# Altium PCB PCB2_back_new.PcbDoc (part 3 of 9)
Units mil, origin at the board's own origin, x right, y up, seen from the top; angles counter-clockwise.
Board outline 6299 x 3937 mil, 4 copper layers (TopLayer, GROUND, VCC, BottomLayer); 253 components, 421 nets, 2085 pads, 712 vias.
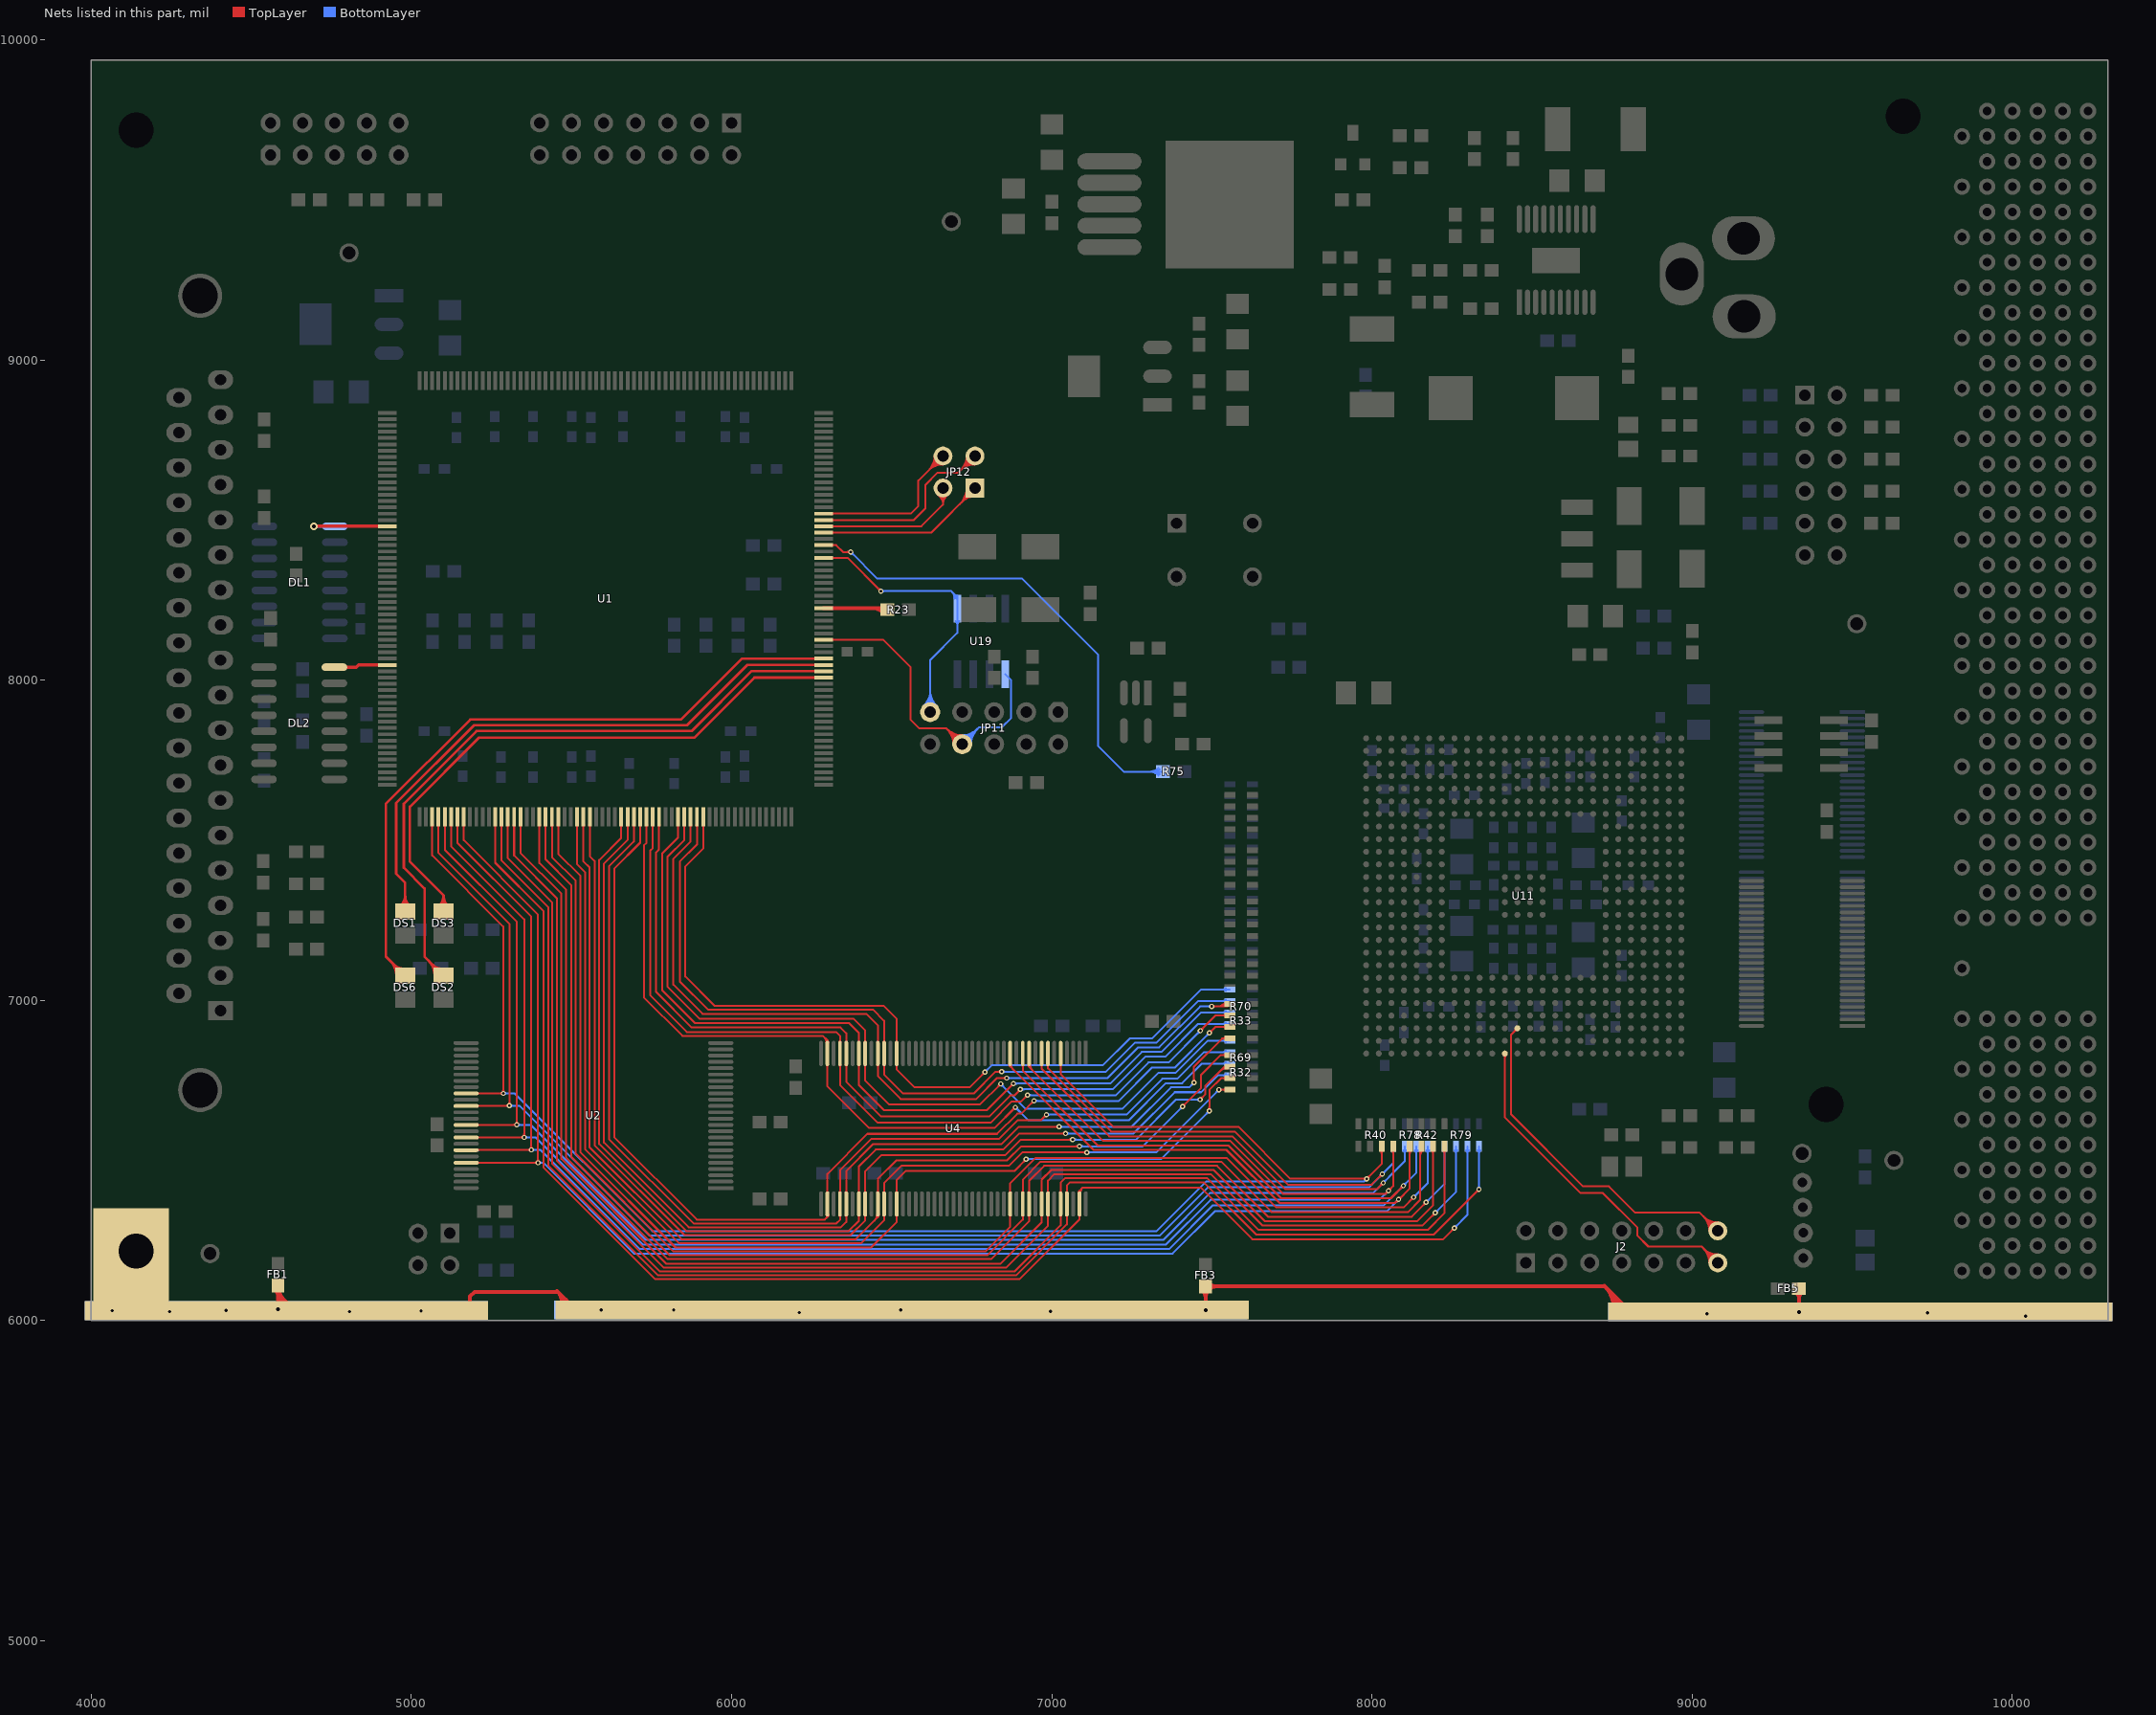
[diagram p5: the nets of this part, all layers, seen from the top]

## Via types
v1: diameter 16, hole 8, TopLayer to BottomLayer, 311 vias
v2: diameter 20, hole 10, TopLayer to BottomLayer, 202 vias
v3: diameter 24, hole 12, TopLayer to BottomLayer, 179 vias
v4: diameter 40, hole 20, TopLayer to BottomLayer, 12 vias
v5: diameter 30, hole 15, TopLayer to BottomLayer, 8 vias

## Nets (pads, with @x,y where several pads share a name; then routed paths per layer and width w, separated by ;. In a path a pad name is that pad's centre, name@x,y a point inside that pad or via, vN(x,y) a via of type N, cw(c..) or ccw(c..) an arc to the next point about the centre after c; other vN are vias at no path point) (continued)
ED02: R40.7 U1.183 U2.33 U4.5 | length 5471.8
  TopLayer w6: U1.183@5062.61,7547.22 cw(c5057.65,7542.26) 5064.66,7542.26 cw(c5071.68,7542.26) U1.183@5066.72,7547.22 ; U1.183@5064.66,7585.69 5064.66,7452.34 5286.73,7230.27 v1(5286.73,6709.27) U2.33@5170.72,6709.27 ; U2.33@5206.24,6707.22 cw(c5211.2,6702.26) 5211.2,6709.28 cw(c5211.2,6716.29) U2.33@5206.24,6711.33 ; v1@5283.19,6705.74 ccw(c5274.65,6697.2) 5274.65,6709.28 ccw(c5274.65,6721.35) 5283.19,6712.81 ccw(c5274.65,6721.35) 5286.73,6721.35 ccw(c5298.8,6721.35) v1@5290.26,6712.81 ; U4.5@7025.21,6798.48 cw(c7020.25,6793.52) 7027.26,6793.52 cw(c7034.27,6793.52) U4.5@7029.31,6798.48 ; U4.5@7027.26,6834 7027.26,6769.74 7193,6604 7584,6604 7745,6443 v1(7984,6443) 8030,6489 R40.7@8030,6543.84 ; v1@7980.46,6439.46 ccw(c7971.93,6430.93) 7971.93,6443 ccw(c7971.93,6455.07) v1@7980.46,6446.54 ; v1@7984,6448 ccw(c7984,6460.07) 7992.54,6451.54 ccw(c8001.07,6443) v1@7989,6443 ; R40.7@8025.76,6531.1 cw(c8015.51,6520.86) 8030,6520.86 cw(c8044.49,6520.86) R40.7@8034.24,6531.1
  BottomLayer w6: v1(5286.73,6709.27) 5321.73,6709.27 5752,6279 7327,6279 7483,6435 7976,6435 ; v1@5290.26,6705.74 cw(c5298.8,6697.2) 5298.8,6709.28 cw(c5298.8,6721.35) v1@5290.26,6712.81 ; v1@7979.01,6442.77 cw(c7968.72,6442.28) 7976,6435 ; v1@7983.77,6438.01 ccw(c7983.28,6427.72) 7976,6435 ; v1(7984,6443) 7976,6435
ED03: R78.8 U1.184 U2.35 U4.7 | length 5638.9
  TopLayer w6: U1.184@5082.29,7547.22 cw(c5077.33,7542.26) 5084.35,7542.26 cw(c5091.36,7542.26) U1.184@5086.4,7547.22 ; U1.184@5084.35,7585.69 5084.35,7460.65 5306,7239 v1(5306,6671) 5171.82,6671 U2.35@5170.72,6669.9 ; U2.35@5206.24,6667.85 cw(c5213.85,6660.25) 5213.85,6671 ; v1@5302.46,6667.46 ccw(c5293.93,6658.93) 5293.93,6671 ccw(c5293.93,6683.07) 5302.46,6674.54 ccw(c5293.93,6683.07) 5306,6683.07 ccw(c5318.07,6683.07) v1@5309.54,6674.54 ; U4.7@6985.84,6798.48 cw(c6980.88,6793.52) 6987.89,6793.52 cw(c6994.9,6793.52) U4.7@6989.94,6798.48 ; U4.7@6987.89,6834 6987.89,6787.11 7185,6590 7571,6590 7737,6424 7999,6424 v1(8032,6457) ; v1@8027,6457 cw(c8014.93,6457) 8023.46,6448.46 cw(c8032,6439.93) v1@8032,6452
  BottomLayer w6: v1(5306,6671) 5337,6671 5743,6265 7336,6265 7487,6416 7991,6416 8066,6491 R78.8@8066,6543.84 ; v1@5309.54,6667.46 cw(c5318.07,6658.93) 5318.07,6671 cw(c5318.07,6683.07) v1@5309.54,6674.54 ; v1@8027,6457 cw(c8014.93,6457) 8023.46,6448.46 cw(c8032,6439.93) v1@8032,6452 ; v1@8032,6462 ccw(c8032,6474.07) 8040.54,6465.54 ccw(c8049.07,6457) v1@8037,6457 ; R78.8@8061.76,6531.1 cw(c8051.51,6520.86) 8066,6520.86 cw(c8080.49,6520.86) R78.8@8070.24,6531.1
ED04: R78.7 U1.185 U2.38 U4.8 | length 5744.6
  TopLayer w6: U1.185@5101.98,7547.22 cw(c5097.02,7542.26) 5104.03,7542.26 cw(c5111.05,7542.26) U1.185@5106.09,7547.22 ; U1.185@5104.03,7585.69 5104.03,7469.97 5329,7245 v1(5329,6611) U2.38@5170.72,6610.85 ; U2.38@5206.25,6608.8 cw(c5211.29,6603.77) 5211.28,6610.89 ; U2.38@5206.24,6612.91 ccw(c5211.12,6617.79) 5211.13,6610.89 ; v1@5325.47,6607.46 ccw(c5316.94,6598.92) 5316.93,6610.99 ccw(c5316.92,6623.06) 5325.46,6614.53 ccw(c5316.93,6623.07) 5329,6623.07 ccw(c5341.07,6623.07) v1@5332.54,6614.54 ; U4.8@6966.15,6798.48 cw(c6961.19,6793.52) 6968.2,6793.52 cw(c6975.22,6793.52) U4.8@6970.26,6798.48 ; U4.8@6968.2,6834 6968.2,6785.8 7179,6575 7564,6575 7729,6410 8015,6410 v1(8035,6430) ; v1@8030,6430 cw(c8017.93,6430) 8026.46,6421.46 cw(c8035,6412.93) v1@8035,6425
  BottomLayer w6: v1(5329,6611) 5372.15,6610.85 5731,6252 7348,6252 7494,6398 8003,6398 8102,6497 R78.7@8102,6543.84 ; v1@5332.52,6607.45 cw(c5341.03,6598.89) 5341.07,6610.96 cw(c5341.11,6623.03) v1@5332.55,6614.52 ; v1@8030,6430 cw(c8017.93,6430) 8026.46,6421.46 cw(c8035,6412.93) v1@8035,6425 ; v1@8035,6435 ccw(c8035,6447.07) 8043.54,6438.54 ccw(c8052.07,6430) v1@8040,6430 ; R78.7@8097.76,6531.1 cw(c8087.51,6520.86) 8102,6520.86 cw(c8116.49,6520.86) R78.7@8106.24,6531.1
ED05: R40.8 U1.186 U2.40 U4.10 | length 5883.2
  TopLayer w6: U1.186@5121.66,7547.22 cw(c5116.7,7542.26) 5123.72,7542.26 cw(c5130.73,7542.26) U1.186@5125.77,7547.22 ; U1.186@5123.72,7585.69 5123.72,7481.28 5352,7253 v1(5352,6572) 5171.24,6572 U2.40@5170.72,6571.48 ; U2.40@5206.24,6569.43 cw(c5212.46,6563.21) 5212.46,6572 ; v1@5348.46,6568.46 ccw(c5339.93,6559.93) 5339.93,6572 ccw(c5339.93,6584.07) 5348.46,6575.54 ccw(c5339.93,6584.07) 5352,6584.07 ccw(c5364.07,6584.07) v1@5355.54,6575.54 ; U4.10@6925.74,6800.54 ccw(c6938.88,6800.54) 6929.59,6791.25 ; U4.10@6928.84,6834 6928.84,6792 7159.84,6561 7557,6561 7722,6396 8042,6396 8066,6420 R40.8@8066,6543.84 ; U4.10@6931.74,6800.54 ccw(c6959.36,6800.54) 6939.83,6781 ; v1@8046.45,6405.45 cw(c8034.38,6405.45) 8042.92,6396.92 cw(c8051.45,6388.38) v1@8051.45,6400.45 ; v1@8051.45,6410.45 ccw(c8051.45,6422.53) 8059.99,6413.99 ccw(c8068.53,6405.45) v1@8056.45,6405.45 ; R40.8@8061.76,6531.1 cw(c8051.51,6520.86) 8066,6520.86 cw(c8080.49,6520.86) R40.8@8070.24,6531.1 ; 6928.84,6793.52 ccw(c6921.82,6793.52) 6926.78,6798.48 cw(c6921.82,6793.52) 6928.84,6793.52 ; 6928.84,6793.52 cw(c6935.85,6793.52) 6930.89,6798.48 ccw(c6935.85,6793.52) 6928.84,6793.52
  BottomLayer w6: v1(5352,6572) 5387,6572 5722,6237 7356,6237 7496,6377 8023,6377 v1(8051.45,6405.45) ; v1@5355.54,6568.46 cw(c5364.07,6559.93) 5364.07,6572 cw(c5364.07,6584.07) v1@5355.54,6575.54 ; v1@8046.45,6405.45 cw(c8034.38,6405.45) 8042.92,6396.92 cw(c8051.45,6388.38) v1@8051.45,6400.45
ED06: R78.6 U1.187 U2.42 U4.11 | length 6015.5
  TopLayer w6: U1.187@5141.35,7547.22 cw(c5136.39,7542.26) 5143.4,7542.26 cw(c5150.42,7542.26) U1.187@5145.46,7547.22 ; U1.187@5143.4,7585.69 5143.4,7491.6 5374,7261 v1(5374,6533) 5171.61,6533 U2.42@5170.72,6532.11 ; U2.42@5206.24,6530.06 cw(c5213.35,6522.95) 5213.35,6533 ; v1@5370.46,6529.46 ccw(c5361.93,6520.93) 5361.93,6533 ccw(c5361.93,6545.07) 5370.46,6536.54 ccw(c5361.93,6545.07) 5374,6545.07 ccw(c5386.07,6545.07) v1@5377.54,6536.54 ; U4.11@6907.1,6798.48 cw(c6902.14,6793.52) 6909.15,6793.52 cw(c6916.16,6793.52) U4.11@6911.2,6798.48 ; U4.11@6909.15,6834 6909.15,6780.85 7143,6547 7551,6547 7716,6382 8059,6382 v1(8098,6421) ; v1@8093,6421 cw(c8080.93,6421) 8089.46,6412.46 cw(c8098,6403.93) v1@8098,6416
  BottomLayer w6: v1(5374,6533) 5403,6533 5713,6223 7366,6223 7503,6360 8037,6360 8138,6461 R78.6@8138,6543.84 ; v1@5377.54,6529.46 cw(c5386.07,6520.93) 5386.07,6533 cw(c5386.07,6545.07) v1@5377.54,6536.54 ; v1@8093,6421 cw(c8080.93,6421) 8089.46,6412.46 cw(c8098,6403.93) v1@8098,6416 ; v1@8098,6426 ccw(c8098,6438.07) 8106.54,6429.54 ccw(c8115.07,6421) v1@8103,6421 ; R78.6@8133.76,6531.1 cw(c8123.51,6520.86) 8138,6520.86 cw(c8152.49,6520.86) R78.6@8142.24,6531.1
ED07: R42.5 U1.188 U2.44 U4.13 | length 6112.5
  TopLayer w6: U1.188@5161.03,7547.22 cw(c5156.07,7542.26) 5163.09,7542.26 cw(c5170.1,7542.26) U1.188@5165.14,7547.22 ; U1.188@5163.09,7585.69 5163.09,7499.91 5395,7268 v1(5395,6492.74) U2.44@5170.72,6492.74 ; U2.44@5206.24,6490.69 cw(c5211.2,6485.73) 5211.2,6492.74 cw(c5211.2,6499.75) U2.44@5206.24,6494.79 ; v1@5391.46,6489.2 ccw(c5382.93,6480.67) 5382.93,6492.74 ccw(c5382.93,6504.81) 5391.46,6496.28 ccw(c5382.93,6504.81) 5395,6504.81 ccw(c5407.07,6504.81) v1@5398.54,6496.28 ; U4.13@6866.69,6800.54 ccw(c6876.88,6800.54) 6869.67,6793.33 ; U4.13@6869.78,6834 6869.78,6793.22 7130,6533 7545,6533 7711,6367 8072,6367 v1(8083,6378) ; U4.13@6872.69,6800.54 ccw(c6897.36,6800.54) 6879.91,6783.09 ; v1@8078,6378 cw(c8065.93,6378) 8074.46,6369.46 cw(c8083,6360.93) v1@8083,6373 ; v1@8083,6383 ccw(c8083,6397.49) 8093.24,6387.24 ; v1@8083.5,6377.5 8118,6412 R42.5@8118,6543.84 ; v1@8088,6378 cw(c8097.66,6378) 8090.83,6384.83 ; R42.5@8113.76,6531.1 cw(c8103.51,6520.86) 8118,6520.86 cw(c8132.49,6520.86) R42.5@8122.24,6531.1 ; 6869.78,6793.52 ccw(c6862.77,6793.52) 6867.73,6798.48 cw(c6862.77,6793.52) 6869.78,6793.52 ; 6869.78,6793.52 cw(c6876.79,6793.52) 6871.83,6798.48 ccw(c6876.79,6793.52) 6869.78,6793.52
  BottomLayer w6: v1(5395,6492.74) 5411.26,6492.74 5695,6209 7377,6209 7509,6341 8046,6341 v1(8083,6378) ; v1@5398.54,6489.2 cw(c5407.07,6480.67) 5407.07,6492.74 cw(c5407.07,6504.81) v1@5398.54,6496.28 ; v1@8078,6378 cw(c8065.93,6378) 8074.46,6369.46 cw(c8083,6360.93) v1@8083,6373
ED08: R78.5 U1.202 U4.74 | length 4387.7
  TopLayer w6: U1.202@5436.62,7547.22 cw(c5431.66,7542.26) 5438.68,7542.26 cw(c5445.69,7542.26) U1.202@5440.73,7547.22 ; U1.202@5438.68,7585.69 5438.68,7447.32 5513,7373 5513,6521 5818,6216 6793,6216 6869.78,6292.78 6869.78,6428.78 6949,6508 7546,6508 7701,6353 8098,6353 v1(8130,6385) ; U4.74@6867.73,6328.48 cw(c6862.77,6323.52) 6869.78,6323.52 cw(c6876.79,6323.52) U4.74@6871.83,6328.48 ; U4.74@6867.73,6399.52 ccw(c6862.77,6404.48) 6869.78,6404.48 ccw(c6876.79,6404.48) U4.74@6871.83,6399.52 ; v1@8125,6385 cw(c8112.93,6385) 8121.46,6376.46 cw(c8130,6367.93) v1@8130,6380
  BottomLayer w6: v1(8130,6385) 8174,6429 R78.5@8174,6543.84 ; v1@8130,6390 ccw(c8130,6402.07) 8138.54,6393.54 ccw(c8147.07,6385) v1@8135,6385 ; R78.5@8169.76,6531.1 cw(c8159.51,6520.86) 8174,6520.86 cw(c8188.49,6520.86) R78.5@8178.24,6531.1
ED09: R42.6 U1.201 U4.76 | length 4395.3
  TopLayer w6: U1.201@5416.94,7547.22 cw(c5411.98,7542.26) 5418.99,7542.26 cw(c5426.01,7542.26) U1.201@5421.05,7547.22 ; U1.201@5418.99,7585.69 5418.99,7440.01 5499,7360 5499,6512 5807,6204 6798,6204 6909.15,6315.15 6909.15,6440.15 6965,6496 7529,6496 7686,6339 8113,6339 8150,6376 8150,6539.84 R42.6@8154,6543.84 ; U4.76@6907.1,6328.48 cw(c6902.14,6323.52) 6909.15,6323.52 cw(c6916.16,6323.52) U4.76@6911.2,6328.48 ; U4.76@6907.1,6399.52 ccw(c6902.14,6404.48) 6909.15,6404.48 ccw(c6916.16,6404.48) U4.76@6911.2,6399.52 ; 8150,6511.2 cw(c8178.14,6511.2) R42.6@8158.24,6531.1 ; 8150,6525.69 cw(c8163.66,6525.69) R42.6@8154,6535.34
ED10: R79.8 U1.200 U4.77 | length 4499.7
  TopLayer w6: U1.200@5397.25,7547.22 cw(c5392.29,7542.26) 5399.31,7542.26 cw(c5406.32,7542.26) U1.200@5401.36,7547.22 ; U1.200@5399.31,7585.69 5399.31,7428.69 5482,7346 5482,6510 5800,6192 6811,6192 6928.84,6309.84 6928.84,6435.84 6976,6483 7516,6483 7675,6324 8124,6324 v1(8169,6369) ; U4.77@6926.78,6328.48 cw(c6921.82,6323.52) 6928.84,6323.52 cw(c6935.85,6323.52) U4.77@6930.89,6328.48 ; U4.77@6926.78,6399.52 ccw(c6921.82,6404.48) 6928.84,6404.48 ccw(c6935.85,6404.48) U4.77@6930.89,6399.52 ; v1@8164,6369 cw(c8151.93,6369) 8160.46,6360.46 cw(c8169,6351.93) v1@8169,6364
  BottomLayer w6: v1(8169,6369) 8226,6426 R79.8@8226,6543.84 ; v1@8169,6374 ccw(c8169,6386.07) 8177.54,6377.54 ccw(c8186.07,6369) v1@8174,6369 ; R79.8@8221.76,6531.1 cw(c8211.51,6520.86) 8226,6520.86 cw(c8240.49,6520.86) R79.8@8230.24,6531.1
ED11: R42.7 U1.197 U4.79 | length 4517.8
  TopLayer w6: U1.197@5338.2,7547.22 cw(c5333.24,7542.26) 5340.25,7542.26 cw(c5347.27,7542.26) U1.197@5342.31,7547.22 ; U1.197@5340.25,7585.69 5340.25,7460.75 5468,7333 5468,6505 5795,6178 6840.2,6178 6968.2,6306 6968.2,6440.2 6998,6470 7506,6470 7666,6310 8141,6310 8190,6359 R42.7@8190,6543.84 ; U4.79@6966.15,6328.48 cw(c6961.19,6323.52) 6968.2,6323.52 cw(c6975.22,6323.52) U4.79@6970.26,6328.48 ; U4.79@6966.15,6399.52 ccw(c6961.19,6404.48) 6968.2,6404.48 ccw(c6975.22,6404.48) U4.79@6970.26,6399.52 ; R42.7@8185.76,6531.1 cw(c8175.51,6520.86) 8190,6520.86 cw(c8204.49,6520.86) R42.7@8194.24,6531.1
ED12: R79.7 U1.196 U4.80 | length 4625
  TopLayer w6: U1.196@5318.51,7547.22 cw(c5313.55,7542.26) 5320.57,7542.26 cw(c5327.58,7542.26) U1.196@5322.62,7547.22 ; U1.196@5320.57,7572.9 5320.57,7452.43 5454,7319 5454,6499 5788,6165 6857,6165 6987.89,6295.89 6987.89,6436.89 7008,6457 7497,6457 7657,6297 8158,6297 v1(8197,6336) ; U4.80@6985.84,6328.48 cw(c6980.88,6323.52) 6987.89,6323.52 cw(c6994.9,6323.52) U4.80@6989.94,6328.48 ; U4.80@6985.84,6399.52 ccw(c6980.88,6404.48) 6987.89,6404.48 ccw(c6994.9,6404.48) U4.80@6989.94,6399.52 ; v1@8192,6336 cw(c8179.93,6336) 8188.46,6327.46 cw(c8197,6318.93) v1@8197,6331
  BottomLayer w6: v1(8197,6336) 8262,6401 R79.7@8262,6543.84 ; v1@8197,6341 ccw(c8197,6353.07) 8205.54,6344.54 ccw(c8214.07,6336) v1@8202,6336 ; R79.7@8257.76,6531.1 cw(c8247.51,6520.86) 8262,6520.86 cw(c8276.49,6520.86) R79.7@8266.24,6531.1
ED13: R42.8 U1.195 U4.82 | length 4631.6
  TopLayer w6: U1.195@5298.83,7547.22 cw(c5293.87,7542.26) 5300.88,7542.26 cw(c5307.9,7542.26) U1.195@5302.94,7547.22 ; U1.195@5300.88,7585.69 5300.88,7444.12 5440,7305 5440,6489 5776,6153 6883,6153 7027.26,6297.26 7027.26,6430.26 7042,6445 7484,6445 7646,6283 8174,6283 8226,6335 R42.8@8226,6543.84 ; U4.82@7025.21,6328.48 cw(c7020.25,6323.52) 7027.26,6323.52 cw(c7034.27,6323.52) U4.82@7029.31,6328.48 ; U4.82@7025.21,6399.52 ccw(c7020.25,6404.48) 7027.26,6404.48 ccw(c7034.27,6404.48) U4.82@7029.31,6399.52 ; R42.8@8221.76,6531.1 cw(c8211.51,6520.86) 8226,6520.86 cw(c8240.49,6520.86) R42.8@8230.24,6531.1
ED14: R79.5 U1.194 U4.83 | length 4756.1
  TopLayer w6: U1.194@5279.14,7547.22 cw(c5274.18,7542.26) 5281.2,7542.26 cw(c5288.21,7542.26) U1.194@5283.25,7547.22 ; U1.194@5281.2,7585.69 5281.2,7436.8 5427,7291 5427,6485 5771,6141 6888,6141 7046.94,6299.94 7046.94,6421.94 7056,6431 7476,6431 7639,6268 8192,6268 v1(8334,6410) ; U4.83@7044.89,6328.48 cw(c7039.93,6323.52) 7046.95,6323.52 cw(c7053.96,6323.52) U4.83@7049,6328.48 ; U4.83@7044.89,6399.52 ccw(c7039.93,6404.48) 7046.95,6404.48 ccw(c7053.96,6404.48) U4.83@7049,6399.52 ; v1@8329,6410 cw(c8316.93,6410) 8325.46,6401.46 cw(c8334,6392.93) v1@8334,6405
  BottomLayer w6: R79.5@8329.76,6531.1 cw(c8319.51,6520.86) 8334,6520.86 cw(c8348.49,6520.86) R79.5@8338.24,6531.1 ; v1@8330.46,6413.54 ccw(c8321.93,6422.07) 8334,6422.07 ccw(c8346.07,6422.07) v1@8337.54,6413.54 ; v1(8334,6410) R79.5@8334,6543.84
ED15: R79.6 U1.193 U4.85 | length 4805
  TopLayer w6: U1.193@5259.46,7547.22 cw(c5254.5,7542.26) 5261.51,7542.26 cw(c5268.53,7542.26) U1.193@5263.57,7547.22 ; U1.193@5261.51,7585.69 5261.51,7429.49 5413,7278 5413,6477 5761,6129 6899,6129 7086.31,6316.31 7086.31,6405.31 7096,6415 ; U4.85@7083.22,6397.33 cw(c7093.9,6397.79) 7086.34,6405.34 ; U4.85@7084.26,6328.48 cw(c7079.3,6323.52) 7086.32,6323.52 cw(c7093.33,6323.52) U4.85@7088.37,6328.48 ; U4.85@7084.26,6399.52 ccw(c7079.3,6404.48) 7086.32,6404.48 ccw(c7093.33,6404.48) U4.85@7088.37,6399.52 ; U4.85@7089.22,6397.59 cw(c7112.42,6398.58) 7096,6415 ; v1@8252,6289 cw(c8239.93,6289) 8248.46,6280.46 cw(c8257,6271.93) v1@8257,6284 ; v1(8257,6289) 8222,6254 7626,6254 7465,6415 7096,6415
  BottomLayer w6: v1(8257,6289) 8298,6330 R79.6@8298,6543.84 ; v1@8257,6294 ccw(c8257,6306.07) 8265.54,6297.54 ccw(c8274.07,6289) v1@8262,6289 ; R79.6@8293.76,6531.1 cw(c8283.51,6520.86) 8298,6520.86 cw(c8312.49,6520.86) R79.6@8302.24,6531.1
ED16: R70.8 U1.226 U4.31 | length 2692.1
  TopLayer w6: U1.226@5909.06,7547.22 cw(c5904.1,7542.26) 5911.12,7542.26 cw(c5918.13,7542.26) U1.226@5913.17,7547.22 ; U1.226@5911.12,7585.69 5911.12,7474.12 5855,7418 5855,7074 5946,6983 6474,6983 6515.45,6941.55 6515.45,6783.55 6571,6728 6743,6728 v1(6791,6776) ; U4.31@6513.4,6798.48 cw(c6508.44,6793.52) 6515.45,6793.52 cw(c6522.46,6793.52) U4.31@6517.5,6798.48 ; U4.31@6513.4,6869.52 ccw(c6508.44,6874.48) 6515.45,6874.48 ccw(c6522.46,6874.48) U4.31@6517.5,6869.52 ; v1@6786,6776 cw(c6773.93,6776) 6782.46,6767.46 cw(c6791,6758.93) v1@6791,6771
  BottomLayer w6: v1(6791,6776) 6812,6797 7159,6797 7243,6881 7313,6881 7466,7034 R70.8@7555.84,7034 ; v1@6791,6781 ccw(c6791,6793.07) 6799.54,6784.54 ccw(c6808.07,6776) v1@6796,6776 ; R70.8@7543.1,7029.76 ccw(c7532.86,7019.51) 7532.86,7034 ccw(c7532.86,7048.49) R70.8@7543.1,7038.24
ED17: R70.7 U1.225 U4.33 | length 2723.5
  TopLayer w6: U1.225@5889.38,7547.22 cw(c5884.42,7542.26) 5891.43,7542.26 cw(c5898.45,7542.26) U1.225@5893.49,7547.22 ; U1.225@5891.43,7585.69 5891.43,7486.43 5838,7433 5838,7059 5926,6971 6441,6971 6476.08,6935.92 6476.08,6767.92 6535,6709 6756,6709 6824,6777 v1(6843,6777) ; U4.33@6474.03,6798.48 cw(c6469.07,6793.52) 6476.08,6793.52 cw(c6483.09,6793.52) U4.33@6478.13,6798.48 ; U4.33@6474.03,6869.52 ccw(c6469.07,6874.48) 6476.08,6874.48 ccw(c6483.09,6874.48) U4.33@6478.13,6869.52 ; v1@6839.46,6773.46 ccw(c6830.93,6764.93) 6830.93,6777 ccw(c6830.93,6789.07) v1@6839.46,6780.54
  BottomLayer w6: v1(6843,6777) 7169,6777 7259,6867 7326,6867 7457,6998 R70.7@7555.84,6998 ; v1@6846.54,6773.46 cw(c6855.07,6764.93) 6855.07,6777 cw(c6855.07,6789.07) v1@6846.54,6780.54 ; R70.7@7543.1,6993.76 ccw(c7532.86,6983.51) 7532.86,6998 ccw(c7532.86,7012.49) R70.7@7543.1,7002.24
ED18: R33.5 U1.224 U4.34 | length 2833.5
  TopLayer w6: U1.224@5869.69,7547.22 cw(c5864.73,7542.26) 5871.75,7542.26 cw(c5878.76,7542.26) U1.224@5873.8,7547.22 ; U1.224@5871.75,7585.69 5871.75,7495.75 5818,7442 5818,7049 5909,6958 6420,6958 6456.4,6921.6 6456.4,6763.6 6528,6692 6764,6692 6829,6757 v1(6859,6757) ; U4.34@6454.34,6798.48 cw(c6449.38,6793.52) 6456.4,6793.52 cw(c6463.41,6793.52) U4.34@6458.45,6798.48 ; U4.34@6454.34,6869.52 ccw(c6449.38,6874.48) 6456.4,6874.48 ccw(c6463.41,6874.48) U4.34@6458.45,6869.52 ; v1@6855.46,6753.46 ccw(c6846.93,6744.93) 6846.93,6757 ccw(c6846.93,6769.07) v1@6855.46,6760.54 ; v1(7499,6981) 7547.84,6981 R33.5@7555.84,6989 ; v1@7502.54,6977.46 cw(c7511.07,6968.93) 7511.07,6981 cw(c7511.07,6993.07) v1@7502.54,6984.54 ; 7513.54,6981 ccw(c7513.54,7022.8) R33.5@7543.1,6993.24 ; 7528.03,6981 ccw(c7528.03,7008.31) R33.5@7547.34,6989 ; R33.5@7542.51,6981 ccw(c7542.51,6993.83) R33.5@7551.59,6984.76
  BottomLayer w6: v1(6859,6757) 7174,6757 7270,6853 7335,6853 7463,6981 v1(7499,6981) ; v1@6862.54,6753.46 cw(c6871.07,6744.93) 6871.07,6757 cw(c6871.07,6769.07) v1@6862.54,6760.54 ; v1@7495.46,6977.46 ccw(c7486.93,6968.93) 7486.93,6981 ccw(c7486.93,6993.07) v1@7495.46,6984.54
ED19: R69.8 U1.223 U4.36 | length 2805
  TopLayer w6: U1.223@5850.01,7547.22 cw(c5845.05,7542.26) 5852.06,7542.26 cw(c5859.08,7542.26) U1.223@5854.12,7547.22 ; U1.223@5852.06,7585.69 5852.06,7501.06 5800,7449 5800,7042 5899,6943 6380,6943 6417.02,6905.98 6417.02,6748.98 6491,6675 6776,6675 v1(6840,6739) ; U4.36@6414.97,6798.48 cw(c6410.01,6793.52) 6417.03,6793.52 ; U4.36@6414.97,6869.52 ccw(c6410.01,6874.48) 6417.03,6874.48 ; 6417.02,6793.52 cw(c6424.04,6793.52) U4.36@6419.08,6798.48 ; 6417.02,6874.48 ccw(c6424.04,6874.48) U4.36@6419.08,6869.52 ; v1@6835,6739 cw(c6822.93,6739) 6831.46,6730.46 cw(c6840,6721.93) v1@6840,6734
  BottomLayer w6: v1@6840,6734 cw(c6840,6721.93) 6848.54,6730.46 cw(c6857.07,6739) v1@6845,6739 ; v1(6840,6739) 6917,6662 7221,6662 7333,6774 7387,6774 7487,6874 R69.8@7555.84,6874 ; R69.8@7543.1,6869.76 ccw(c7532.86,6859.51) 7532.86,6874 ccw(c7532.86,6888.49) R69.8@7543.1,6878.24
ED20: R70.6 U1.222 U4.37 | length 2817.9
  TopLayer w6: U1.222@5830.32,7547.22 cw(c5825.36,7542.26) 5832.38,7542.26 cw(c5839.39,7542.26) U1.222@5834.43,7547.22 ; U1.222@5832.38,7585.69 5832.38,7508.38 5783,7459 5783,7031 5885,6929 6366,6929 6397.34,6897.66 6397.34,6735.66 6476,6657 6797,6657 v1(6880,6740) ; U4.37@6395.29,6798.48 cw(c6390.33,6793.52) 6397.34,6793.52 cw(c6404.35,6793.52) U4.37@6399.39,6798.48 ; U4.37@6395.29,6869.52 ccw(c6390.33,6874.48) 6397.34,6874.48 ccw(c6404.35,6874.48) U4.37@6399.39,6869.52 ; v1@6875,6740 cw(c6862.93,6740) 6871.46,6731.46 cw(c6880,6722.93) v1@6880,6735
  BottomLayer w6: v1(6880,6740) 7182,6740 7281,6839 7343,6839 7466,6962 R70.6@7555.84,6962 ; v1@6883.54,6736.46 cw(c6892.07,6727.93) 6892.07,6740 cw(c6892.07,6752.07) v1@6883.54,6743.54 ; R70.6@7543.1,6957.76 ccw(c7532.86,6947.51) 7532.86,6962 ccw(c7532.86,6976.49) R70.6@7543.1,6966.24
ED21: R70.5 U1.219 U4.39 | length 2818.4
  TopLayer w6: U1.219@5771.27,7547.22 cw(c5766.31,7542.26) 5773.32,7542.26 cw(c5780.34,7542.26) U1.219@5775.38,7547.22 ; U1.219@5773.32,7585.69 5773.32,7471.32 5764,7462 5764,7026 5875,6915 6340,6915 6357.97,6897.03 6357.97,6746.03 6467,6637 6804,6637 6870,6703 6883,6703 v1(6902,6722) ; U4.39@6355.92,6798.48 cw(c6350.96,6793.52) 6357.97,6793.52 cw(c6364.98,6793.52) U4.39@6360.02,6798.48 ; U4.39@6355.92,6869.52 ccw(c6350.96,6874.48) 6357.97,6874.48 ccw(c6364.98,6874.48) U4.39@6360.02,6869.52 ; v1@6897,6722 cw(c6884.93,6722) 6893.46,6713.46 cw(c6902,6704.93) v1@6902,6717
  BottomLayer w6: v1(6902,6722) 7190,6722 7292,6824 7354,6824 7456,6926 R70.5@7555.84,6926 ; v1@6905.54,6718.46 cw(c6914.07,6709.93) 6914.07,6722 cw(c6914.07,6734.07) v1@6905.54,6725.54 ; R70.5@7543.1,6921.76 ccw(c7532.86,6911.51) 7532.86,6926 ccw(c7532.86,6940.49) R70.5@7543.1,6930.24
ED22: R33.6 U1.218 U4.40 | length 2909
  TopLayer w6: U1.218@5751.58,7547.22 cw(c5746.62,7542.26) 5753.64,7542.26 cw(c5760.65,7542.26) U1.218@5755.69,7547.22 ; U1.218@5753.64,7585.69 5753.64,7475.64 5745,7467 5745,7016 5860,6901 6326,6901 6338.28,6888.72 6338.28,6735.72 6456,6618 6809,6618 6875,6684 6904,6684 v1(6924,6704) ; U4.40@6336.23,6798.48 cw(c6331.27,6793.52) 6338.28,6793.52 cw(c6345.3,6793.52) U4.40@6340.34,6798.48 ; U4.40@6336.23,6869.52 ccw(c6331.27,6874.48) 6338.28,6874.48 ccw(c6345.3,6874.48) U4.40@6340.34,6869.52 ; v1@6919,6704 cw(c6906.93,6704) 6915.46,6695.46 cw(c6924,6686.93) v1@6924,6699 ; v1(7464,6905) 7512,6953 R33.6@7555.84,6953 ; v1@7464,6910 ccw(c7464,6922.07) 7472.54,6913.54 ccw(c7481.07,6905) v1@7469,6905 ; R33.6@7543.1,6948.76 ccw(c7532.86,6938.51) 7532.86,6953 ccw(c7532.86,6967.49) R33.6@7543.1,6957.24
  BottomLayer w6: v1(6924,6704) 7200,6704 7302,6806 7365,6806 v1(7464,6905) ; v1@6927.54,6700.46 cw(c6936.07,6691.93) 6936.07,6704 cw(c6936.07,6716.07) v1@6927.54,6707.54 ; v1@7459,6905 cw(c7446.93,6905) 7455.46,6896.46 cw(c7464,6887.93) v1@7464,6900
ED23: R69.6 U1.217 U4.42 | length 2902.7
  TopLayer w6: U1.217@5731.9,7547.22 cw(c5726.94,7542.26) 5733.95,7542.26 cw(c5740.97,7542.26) U1.217@5736.01,7547.22 ; U1.217@5733.95,7585.69 5733.95,7491.95 5726,7484 5726,7009 5846,6889 6285,6889 6298.91,6875.09 6298.91,6731.09 6429,6601 6821,6601 v1(6886,6666) ; 6288.57,6885.43 cw(c6270.6,6867.46) U4.42@6296.01,6867.46 ; U4.42@6296.86,6798.48 cw(c6291.9,6793.52) 6298.91,6793.52 cw(c6305.93,6793.52) U4.42@6300.97,6798.48 ; U4.42@6296.86,6869.52 ccw(c6291.9,6874.48) 6298.91,6874.48 ccw(c6305.93,6874.48) U4.42@6300.97,6869.52 ; 6298.81,6875.19 cw(c6291.08,6867.46) U4.42@6302.01,6867.46 ; v1@6881,6666 cw(c6868.93,6666) 6877.46,6657.46 cw(c6886,6648.93) v1@6886,6661
  BottomLayer w6: v1@6886,6661 cw(c6886,6648.93) 6894.54,6657.46 cw(c6903.07,6666) v1@6891,6666 ; v1(6886,6666) 6927,6625 7240,6625 7356,6741 7407,6741 7468,6802 R69.6@7555.84,6802 ; R69.6@7543.1,6797.76 ccw(c7532.86,6787.51) 7532.86,6802 ccw(c7532.86,6816.49) R69.6@7543.1,6806.24
ED24: R33.7 U1.216 U4.45 | length 3503.3
  TopLayer w6: U1.216@5712.21,7547.22 cw(c5707.25,7542.26) 5714.27,7542.26 cw(c5721.28,7542.26) U1.216@5716.32,7547.22 ; U1.216@5714.27,7585.69 5714.27,7492.27 5633,7411 5633,6573 5891,6315 6291,6315 6298.91,6322.91 ; 6294.81,6318.81 ccw(c6288.59,6325.03) U4.45@6296.35,6329.17 ; U4.45@6296.86,6399.52 ccw(c6291.9,6404.48) 6298.91,6404.48 ccw(c6305.93,6404.48) U4.45@6300.97,6399.52 ; U4.45@6298.91,6364 6298.91,6457.91 6424,6583 6829,6583 6892,6646 6904,6646 v1(6944,6686) ; 6300.54,6324.54 ccw(c6296.06,6329.01) U4.45@6301.65,6331.99 ; v1@6939,6686 cw(c6926.93,6686) 6935.46,6677.46 cw(c6944,6668.93) v1@6944,6681 ; v1(7492,6898) 7511,6917 R33.7@7555.84,6917 ; v1@7492,6903 ccw(c7492,6915.07) 7500.54,6906.54 ccw(c7509.07,6898) v1@7497,6898 ; R33.7@7543.1,6912.76 ccw(c7532.86,6902.51) 7532.86,6917 ccw(c7532.86,6931.49) R33.7@7543.1,6921.24
  BottomLayer w6: v1(6944,6686) 7209,6686 7313,6790 7384,6790 v1(7492,6898) ; v1@6947.54,6682.46 cw(c6956.07,6673.93) 6956.07,6686 cw(c6956.07,6698.07) v1@6947.54,6689.54 ; v1@7487,6898 cw(c7474.93,6898) 7483.46,6889.46 cw(c7492,6880.93) v1@7492,6893
ED25: R69.7 U1.215 U4.47 | length 3505.2
  TopLayer w6: U1.215@5692.53,7547.22 cw(c5687.57,7542.26) 5694.58,7542.26 cw(c5701.6,7542.26) U1.215@5696.64,7547.22 ; U1.215@5694.58,7585.69 5694.58,7495.58 5617,7418 5617,6567 5881,6303 6327,6303 6338.28,6314.28 6338.28,6469.28 6435.88,6566.88 6834.88,6566.88 6893,6625 6965.12,6625 v1(6983.12,6643) ; U4.47@6336.23,6328.48 cw(c6331.27,6323.52) 6338.28,6323.52 cw(c6345.3,6323.52) U4.47@6340.34,6328.48 ; U4.47@6336.23,6399.52 ccw(c6331.27,6404.48) 6338.28,6404.48 ccw(c6345.3,6404.48) U4.47@6340.34,6399.52 ; v1@6978.12,6643 cw(c6966.05,6643) 6974.59,6634.46 cw(c6983.12,6625.93) v1@6983.12,6638
  BottomLayer w6: v1(6983.12,6643) 7233,6643 7345,6755 7392,6755 7475,6838 R69.7@7555.84,6838 ; v1@6986.66,6639.46 cw(c6995.19,6630.93) 6995.19,6643 cw(c6995.19,6655.07) v1@6986.66,6646.54 ; R69.7@7543.1,6833.76 ccw(c7532.86,6823.51) 7532.86,6838 ccw(c7532.86,6852.49) R69.7@7543.1,6842.24
ED26: R33.8 U1.214 U4.48 | length 3623.4
  TopLayer w6: U1.214@5672.84,7547.22 cw(c5667.88,7542.26) 5674.9,7542.26 cw(c5681.91,7542.26) U1.214@5676.95,7547.22 ; U1.214@5674.9,7585.69 5674.9,7500.9 5601,7427 5601,6556 5866,6291 6341,6291 6357.97,6307.97 6357.97,6466.97 6442,6551 6843,6551 6897,6605 v1(7023,6605) ; U4.48@6355.92,6328.48 cw(c6350.96,6323.52) 6357.97,6323.52 cw(c6364.98,6323.52) U4.48@6360.02,6328.48 ; U4.48@6355.92,6399.52 ccw(c6350.96,6404.48) 6357.97,6404.48 ccw(c6364.98,6404.48) U4.48@6360.02,6399.52 ; v1@7019.46,6601.46 ccw(c7010.93,6592.93) 7010.93,6605 ccw(c7010.93,6617.07) v1@7019.46,6608.54 ; v1@7440.46,6746.54 ccw(c7431.93,6755.07) 7444,6755.07 ccw(c7456.07,6755.07) v1@7447.54,6746.54 ; v1(7444,6743) 7444,6793 7532,6881 R33.8@7555.84,6881 ; R33.8@7543.1,6876.76 ccw(c7532.86,6866.51) 7532.86,6881 ccw(c7532.86,6895.49) R33.8@7543.1,6885.24
  BottomLayer w6: v1(7023,6605) 7249,6605 7372,6728 7429,6728 v1(7444,6743) ; v1@7026.54,6601.46 cw(c7035.07,6592.93) 7035.07,6605 cw(c7035.07,6617.07) v1@7026.54,6608.54 ; v1@7439,6743 cw(c7426.93,6743) 7435.46,6734.46 cw(c7444,6725.93) v1@7444,6738
ED27: R69.5 U1.213 U4.50 | length 3541.1
  TopLayer w6: U1.213@5653.16,7547.22 cw(c5648.2,7542.26) 5655.21,7542.26 cw(c5662.23,7542.26) U1.213@5657.27,7547.22 ; U1.213@5655.21,7585.69 5655.21,7507.21 5586,7438 5586,6551 5858,6279 6365.34,6279 6397.34,6311 6397.34,6481.34 6450,6534 6848,6534 6898,6584 v1(7043,6584) ; U4.50@6395.29,6328.48 cw(c6390.33,6323.52) 6397.34,6323.52 cw(c6404.35,6323.52) U4.50@6399.39,6328.48 ; U4.50@6395.29,6399.52 ccw(c6390.33,6404.48) 6397.34,6404.48 ccw(c6404.35,6404.48) U4.50@6399.39,6399.52 ; v1@7039.46,6580.46 ccw(c7030.93,6571.93) 7030.93,6584 ccw(c7030.93,6596.07) v1@7039.46,6587.54
  BottomLayer w6: v1(7043,6584) 7255,6584 7384,6713 7466,6713 7519,6766 R69.5@7555.84,6766 ; v1@7046.54,6580.46 cw(c7055.07,6571.93) 7055.07,6584 cw(c7055.07,6596.07) v1@7046.54,6587.54 ; R69.5@7543.1,6761.76 ccw(c7532.86,6751.51) 7532.86,6766 ccw(c7532.86,6780.49) R69.5@7543.1,6770.24
ED28: R32.6 U1.208 U4.51 | length 3615.7
  TopLayer w6: U1.208@5554.73,7547.22 cw(c5549.77,7542.26) 5556.79,7542.26 cw(c5563.8,7542.26) U1.208@5558.84,7547.22 ; U1.208@5556.79,7585.69 5556.79,7450.21 5572,7435 5572,6547 5852,6267 6371,6267 6417.02,6313.02 6417.02,6466.02 6467,6516 6854,6516 6903,6565 v1(7065,6565) ; U4.51@6414.97,6328.48 cw(c6410.01,6323.52) 6417.03,6323.52 ; U4.51@6414.97,6399.52 ccw(c6410.01,6404.48) 6417.03,6404.48 ; 6417.02,6323.52 cw(c6424.04,6323.52) U4.51@6419.08,6328.48 ; 6417.02,6404.48 ccw(c6424.04,6404.48) U4.51@6419.08,6399.52 ; v1@7061.46,6561.46 ccw(c7052.93,6552.93) 7052.93,6565 ccw(c7052.93,6577.07) v1@7061.46,6568.54 ; v1(7463,6690) 7479,6706 7479,6732 7540,6793 R32.6@7555.84,6793 ; v1@7463,6695 ccw(c7463,6707.07) 7471.54,6698.54 ccw(c7480.07,6690) v1@7468,6690 ; 7524.57,6777.57 cw(c7547.34,6754.79) R32.6@7547.34,6787 ; 7534.81,6787.81 cw(c7547.34,6775.27) R32.6@7547.34,6793
  BottomLayer w6: v1(7065,6565) 7263,6565 7388,6690 v1(7463,6690) ; v1@7068.54,6561.46 cw(c7077.07,6552.93) 7077.07,6565 cw(c7077.07,6577.07) v1@7068.54,6568.54 ; v1@7459.46,6686.46 ccw(c7450.93,6677.93) 7450.93,6690 ccw(c7450.93,6702.07) v1@7459.46,6693.54
ED29: R32.5 U1.207 U4.53 | length 3665.9
  TopLayer w6: U1.207@5535.05,7547.22 cw(c5530.09,7542.26) 5537.1,7542.26 cw(c5544.12,7542.26) U1.207@5539.16,7547.22 ; U1.207@5537.1,7585.69 5537.1,7433.9 5556,7415 5556,6541 5843,6254 6388,6254 6456.4,6322.4 6456.4,6442.4 6514,6500 6860,6500 6904,6544 v1(7086,6544) ; 6445.68,6311.68 ccw(c6426.82,6330.54) U4.53@6453.49,6330.54 ; U4.53@6454.34,6328.48 cw(c6449.38,6323.52) 6456.4,6323.52 cw(c6463.41,6323.52) U4.53@6458.45,6328.48 ; U4.53@6454.34,6399.52 ccw(c6449.38,6404.48) 6456.4,6404.48 ccw(c6463.41,6404.48) U4.53@6458.45,6399.52 ; 6455.92,6321.92 ccw(c6447.31,6330.54) U4.53@6459.49,6330.54 ; v1@7082.46,6540.46 ccw(c7073.93,6531.93) 7073.93,6544 ccw(c7073.93,6556.07) v1@7082.46,6547.54 ; v1(7408.12,6668.12) 7465,6725 7465,6766 7528,6829 R32.5@7555.84,6829 ; v1@7408.12,6673.12 ccw(c7408.12,6685.19) 7416.65,6676.65 ccw(c7425.19,6668.12) v1@7413.12,6668.12 ; R32.5@7543.1,6824.76 ccw(c7532.86,6814.51) 7532.86,6829 ccw(c7532.86,6843.49) R32.5@7543.1,6833.24
  BottomLayer w6: v1(7086,6544) 7284,6544 v1(7408.12,6668.12) ; v1@7089.54,6540.46 cw(c7098.07,6531.93) 7098.07,6544 cw(c7098.07,6556.07) v1@7089.54,6547.54 ; v1@7403.12,6668.12 cw(c7391.05,6668.12) 7399.58,6659.58 cw(c7408.12,6651.05) v1@7408.12,6663.12
ED30: R32.8 U1.206 U4.54 | length 3594.9
  TopLayer w6: U1.206@5515.36,7547.22 cw(c5510.4,7542.26) 5517.42,7542.26 cw(c5524.43,7542.26) U1.206@5519.47,7547.22 ; U1.206@5517.42,7585.69 5517.42,7424.58 5542,7400 5542,6535 5836,6241 6404,6241 6476.08,6313.08 6476.08,6429 6530.08,6483 6866,6483 6908,6525 v1(7109,6525) ; U4.54@6474.03,6328.48 cw(c6469.07,6323.52) 6476.08,6323.52 cw(c6483.09,6323.52) U4.54@6478.13,6328.48 ; U4.54@6474.03,6399.52 ccw(c6469.07,6404.48) 6476.08,6404.48 ccw(c6483.09,6404.48) U4.54@6478.13,6399.52 ; v1@7105.46,6521.46 ccw(c7096.93,6512.93) 7096.93,6525 ccw(c7096.93,6537.07) v1@7105.46,6528.54 ; v1(7522,6721) R32.8@7555.84,6721 ; v1@7525.54,6717.46 cw(c7534.07,6708.93) 7534.07,6721 cw(c7534.07,6733.07) v1@7525.54,6724.54 ; R32.8@7543.1,6716.76 ccw(c7532.86,6706.51) 7532.86,6721 ccw(c7532.86,6735.49) R32.8@7543.1,6725.24
  BottomLayer w6: v1(7109,6525) 7326,6525 v1(7522,6721) ; v1@7112.54,6521.46 cw(c7121.07,6512.93) 7121.07,6525 cw(c7121.07,6537.07) v1@7112.54,6528.54 ; v1@7517,6721 cw(c7504.93,6721) 7513.46,6712.46 cw(c7522,6703.93) v1@7522,6716
ED31: R32.7 U1.203 U4.56 | length 3706.6
  TopLayer w6: U1.203@5456.31,7547.22 cw(c5451.35,7542.26) 5458.36,7542.26 cw(c5465.38,7542.26) U1.203@5460.42,7547.22 ; U1.203@5458.36,7585.69 5458.36,7457.64 5528,7388 5528,6525 5825,6228 6436,6228 6515.45,6307.45 6515.45,6439.45 6543,6467 6883,6467 v1(6920,6504) ; U4.56@6513.4,6328.48 cw(c6508.44,6323.52) 6515.45,6323.52 cw(c6522.46,6323.52) U4.56@6517.5,6328.48 ; U4.56@6513.4,6399.52 ccw(c6508.44,6404.48) 6515.45,6404.48 ccw(c6522.46,6404.48) U4.56@6517.5,6399.52 ; v1@6915,6504 cw(c6902.93,6504) 6911.46,6495.46 cw(c6920,6486.93) v1@6920,6499 ; v1@7488.46,6658.54 ccw(c7479.93,6667.07) 7492,6667.07 ccw(c7504.07,6667.07) v1@7495.54,6658.54 ; v1(7492,6655) 7492,6720 7529,6757 R32.7@7555.84,6757 ; R32.7@7543.1,6752.76 ccw(c7532.86,6742.51) 7532.86,6757 ccw(c7532.86,6771.49) R32.7@7543.1,6761.24
  BottomLayer w6: v1(6920,6504) 7341,6504 v1(7492,6655) ; v1@6923.54,6500.46 cw(c6932.07,6491.93) 6932.07,6504 cw(c6932.07,6516.07) v1@6923.54,6507.54 ; v1@7487,6655 cw(c7474.93,6655) 7483.46,6646.46 cw(c7492,6637.93) v1@7492,6650
EMU0: J2.13 U11.A15 | length 1325
  TopLayer w6: U11.A15@8410.4,6829.58 cw(c8399.73,6818.91) 8414.82,6818.91 cw(c8429.91,6818.91) U11.A15@8419.24,6829.58 ; U11.A15@8414.82,6834 8414.82,6634.18 8651,6398 8721,6398 8828,6291 8828,6266 8863,6231 9029,6231 J2.13@9080,6180 ; J2.13@9053.47,6180 ccw(c8989.43,6180) 9034.71,6225.29 ccw(c9080,6270.57) J2.13@9080,6206.53 ; J2.13@9059.47,6180 ccw(c9009.91,6180) 9044.96,6215.04 ccw(c9080,6250.09) J2.13@9080,6200.53 ; J2.13@9065.47,6180 ccw(c9030.4,6180) 9055.2,6204.8 ccw(c9080,6229.6) J2.13@9080,6194.53
EMU1: J2.14 U11.C14 | length 1331.1
  TopLayer w6: U11.C14@8447.94,6912.74 cw(c8432.84,6912.74) 8443.52,6902.07 cw(c8454.19,6891.39) U11.C14@8454.19,6906.49 ; U11.C14@8454.19,6912.74 8434,6892.55 8434,6644 8659,6419 8740,6419 8822,6337 9023,6337 J2.14@9080,6280 ; J2.14@9053.47,6280 ccw(c8989.43,6280) 9034.71,6325.29 ccw(c9080,6370.57) J2.14@9080,6306.53 ; J2.14@9059.47,6280 ccw(c9009.91,6280) 9044.96,6315.04 ccw(c9080,6350.09) J2.14@9080,6300.53 ; J2.14@9065.47,6280 ccw(c9030.4,6280) 9055.2,6304.8 ccw(c9080,6329.6) J2.14@9080,6294.53
EN1: DL1.1 U1.139 | length 295.5
  TopLayer w10: v3@4695,8480 v3(4695.38,8480.38) U1.139@4924.9,8480.38
  BottomLayer w10: v3(4695.38,8480.38) 4760.42,8480.38 DL1.1@4760.7,8480.1
EN2: DL2.16 U1.161 | length 168.6
  TopLayer w10: DL2.16@4759.3,8040.1 4827.1,8040.1 4834.31,8047.31 U1.161@4924.9,8047.31
FPGA_ASDO: JP11.9 U1.37 U19.5 | length 1257
  TopLayer w6: U1.37@6274.31,8381.95 6362.05,8381.95 v1(6466,8278) ; U1.37@6312.78,8379.9 cw(c6317.74,8374.94) 6317.74,8381.95 cw(c6317.74,8388.97) U1.37@6312.78,8384.01 ; v1@6461,8278 ccw(c6448.93,8278) 6457.46,8286.54 ccw(c6466,8295.07) v1@6466,8283
  BottomLayer w6: v1(6466,8278) 6686,8278 6705,8259 6705,8147 6620,8062 JP11.9@6620,7900 ; v1@6469.54,8274.46 cw(c6478.07,8265.93) 6478.07,8278 cw(c6478.07,8290.07) v1@6469.54,8281.54 ; JP11.9@6600.2,7919.8 ccw(c6552.4,7967.6) 6620,7967.6 ccw(c6687.6,7967.6) JP11.9@6639.8,7919.8 ; JP11.9@6604.44,7915.56 ccw(c6566.89,7953.11) 6620,7953.11 ccw(c6673.11,7953.11) JP11.9@6635.56,7915.56 ; JP11.9@6608.69,7911.31 ccw(c6581.37,7938.63) 6620,7938.63 ccw(c6658.63,7938.63) JP11.9@6631.31,7911.31 ; 6686.32,8277.68 cw(c6662.5,8253.86) U19.5@6696.19,8253.86 ; 6696.57,8267.43 cw(c6682.99,8253.86) U19.5@6702.19,8253.86 ; U19.5@6698.77,8184.64 cw(c6683.73,8169.59) 6705,8169.59 cw(c6726.27,8169.59) U19.5@6711.23,8184.64 ; U19.5@6698.74,8265.26 ccw(c6705,8271.53) U19.5@6705,8262.67
FPGA_IO18: DS3.1 U1.18 | length 1957.6
  TopLayer w8: DS3.1@5085.06,7292.99 ccw(c5051.51,7328) 5100,7328 ; DS3.1@5090.6,7287.21 ccw(c5069.48,7309.25) 5100,7309.25 ccw(c5130.52,7309.25) DS3.1@5109.4,7287.21 ; DS3.1@5100,7277.4 5100,7328 ; DS3.1@5114.94,7292.99 cw(c5148.49,7328) 5100,7328 ; U1.18@6287.1,8007.94 6070.94,8007.94 5883,7820 5210,7820 4995,7605 4995,7433 5100,7328
FPGA_IO19: DS2.1 U1.19 | length 2189.2
  TopLayer w8: 5053.06,7124.34 cw(c5006.12,7077.4) DS2.1@5072.5,7077.4 ; 5066.72,7110.68 cw(c5033.44,7077.4) DS2.1@5080.5,7077.4 ; 5067.32,7110.08 ccw(c5094.09,7136.86) DS2.1@5094.09,7098.99 ; DS2.1@5100,7077.4 5041,7136.4 5041,7349 4976,7414 4976,7614 5203,7841 5875,7841 6061.62,8027.62 U1.19@6287.1,8027.62
FPGA_IO20: DS1.1 U1.20 | length 1997.4
  TopLayer w8: DS1.1@4964.73,7292.67 ccw(c4927.88,7329.53) 4980,7329.53 ccw(c5032.12,7329.53) DS1.1@4995.27,7292.67 ; DS1.1@4970.39,7287.01 ccw(c4947.19,7310.21) 4980,7310.21 ccw(c5012.81,7310.21) DS1.1@4989.61,7287.01 ; DS1.1@4980,7277.4 4980,7367 4952,7395 4952,7616 5195,7859 5860,7859 6048.31,8047.31 U1.20@6287.1,8047.31
FPGA_IO21: DS6.1 U1.21 | length 2234.4
  TopLayer w8: 4933.06,7124.34 cw(c4886.12,7077.4) DS6.1@4952.5,7077.4 ; 4946.72,7110.68 cw(c4913.44,7077.4) DS6.1@4960.5,7077.4 ; 4947.32,7110.08 ccw(c4974.09,7136.86) DS6.1@4974.09,7098.99 ; DS6.1@4980,7077.4 4920,7137.4 4920,7613 5184,7877 5842,7877 6031.99,8066.99 U1.21@6287.1,8066.99
FPGA_IO41: JP12.1 U1.41 | length 789.7
  TopLayer w6: U1.41@6274.31,8460.69 6623.69,8460.69 6760,8597 JP12.1@6760,8600 ; U1.41@6312.78,8458.64 cw(c6317.74,8453.68) 6317.74,8460.69 cw(c6317.74,8467.71) U1.41@6312.78,8462.75 ; 6712.59,8549.59 ccw(c6662.19,8600) JP12.1@6733.47,8600 ; 6719.84,8556.84 cw(c6760,8516.67) JP12.1@6760,8573.47 ; 6722.84,8559.84 ccw(c6682.67,8600) JP12.1@6739.47,8600 ; 6730.08,8567.08 cw(c6760,8537.16) JP12.1@6760,8579.47 ; 6733.08,8570.08 ccw(c6703.16,8600) JP12.1@6745.47,8600 ; JP12.1@6740.32,8577.32 cw(c6760,8557.64) JP12.1@6760,8585.47
FPGA_IO42: JP12.2 U1.42 | length 602.9
  TopLayer w6: U1.42@6274.31,8480.38 6592.38,8480.38 6660,8548 ; U1.42@6312.78,8478.32 cw(c6317.74,8473.36) 6317.74,8480.38 cw(c6317.74,8487.39) U1.42@6312.78,8482.43 ; JP12.2@6644.43,8578.52 cw(c6622.3,8548) 6660,8548 ; JP12.2@6647.95,8583.38 cw(c6630.83,8559.76) 6660,8559.76 cw(c6689.17,8559.76) JP12.2@6672.05,8583.38 ; JP12.2@6660,8600 6660,8548 ; JP12.2@6675.57,8578.52 ccw(c6697.7,8548) 6660,8548
FPGA_IO43: JP12.3 U1.43 | length 856.4
  TopLayer w6: U1.43@6274.31,8500.06 6569.06,8500.06 6605,8536 6605,8610 6643,8648 6708,8648 JP12.3@6760,8700 ; U1.43@6312.78,8498.01 cw(c6317.74,8493.05) 6317.74,8500.06 cw(c6317.74,8507.08) U1.43@6312.78,8502.12 ; JP12.3@6733.47,8700 cw(c6669.43,8700) 6714.71,8654.71 cw(c6760,8609.43) JP12.3@6760,8673.47 ; JP12.3@6739.47,8700 cw(c6689.91,8700) 6724.96,8664.96 cw(c6760,8629.91) JP12.3@6760,8679.47 ; JP12.3@6745.47,8700 cw(c6710.4,8700) 6735.2,8675.2 cw(c6760,8650.4) JP12.3@6760,8685.47
FPGA_IO44: JP12.4 U1.44 | length 751.8
  TopLayer w6: U1.44@6274.31,8519.75 6559.75,8519.75 6583,8543 6583,8623 JP12.4@6660,8700 ; U1.44@6312.78,8517.69 cw(c6317.74,8512.73) 6317.74,8519.75 cw(c6317.74,8526.76) U1.44@6312.78,8521.8 ; JP12.4@6633.47,8700 cw(c6569.43,8700) 6614.71,8654.71 cw(c6660,8609.43) JP12.4@6660,8673.47 ; JP12.4@6639.47,8700 cw(c6589.91,8700) 6624.96,8664.96 cw(c6660,8629.91) JP12.4@6660,8679.47 ; JP12.4@6645.47,8700 cw(c6610.4,8700) 6635.2,8675.2 cw(c6660,8650.4) JP12.4@6660,8685.47
FPGA_NCSO: JP11.8 U1.24 U19.1 | length 1516.6
  TopLayer w6: U1.24@6276.35,8124 U1.24@6287.1,8126.05 6472.95,8126.05 6558,8041 6558,7877 6586,7849 6671,7849 JP11.8@6720,7800 ; U1.24@6312.78,8123.99 cw(c6317.74,8119.03) 6317.74,8126.05 cw(c6317.74,8133.06) U1.24@6312.78,8128.1 ; JP11.8@6692,7800 ccw(c6624.4,7800) 6672.2,7847.8 ccw(c6720,7895.6) JP11.8@6720,7828 ; JP11.8@6698,7800 ccw(c6644.89,7800) 6682.44,7837.56 ccw(c6720,7875.11) JP11.8@6720,7822 ; JP11.8@6704,7800 ccw(c6665.37,7800) 6692.69,7827.31 ccw(c6720,7854.63) JP11.8@6720,7816
  BottomLayer w6: JP11.8@6720,7800 6773,7853 6844,7853 6873,7882 6873,7999.64 U19.1@6855,8017.64 ; JP11.8@6720,7816 ccw(c6720,7854.63) 6747.31,7827.31 ccw(c6774.63,7800) JP11.8@6736,7800 ; JP11.8@6720,7822 ccw(c6720,7875.11) 6757.56,7837.56 ccw(c6795.11,7800) JP11.8@6742,7800 ; JP11.8@6720,7828 ccw(c6720,7895.6) 6767.8,7847.8 ccw(c6815.6,7800) JP11.8@6748,7800
FPGA_PLLOUT: R75.1 U1.39 | length 1684.9
  TopLayer w6: U1.39@6274.31,8421.32 6326.68,8421.32 6348,8400 v1(6372,8400) ; U1.39@6312.78,8419.27 cw(c6317.74,8414.31) 6317.74,8421.32 cw(c6317.74,8428.34) U1.39@6312.78,8423.38 ; v1@6368.46,8396.46 ccw(c6359.93,8387.93) 6359.93,8400 ccw(c6359.93,8412.07) v1@6368.46,8403.54
  BottomLayer w6: v1@6372,8395 cw(c6372,8382.93) 6380.54,8391.46 cw(c6389.07,8400) v1@6377,8400 ; v1(6372,8400) 6455,8317 6907,8317 7144,8080 7144,7795 7225,7714 R75.1@7346.54,7714 ; R75.1@7332.77,7702.2 ccw(c7304.29,7673.72) 7304.29,7714 ccw(c7304.29,7754.28) R75.1@7332.77,7725.8 ; R75.1@7337.01,7706.44 ccw(c7318.77,7688.2) 7318.77,7714 ccw(c7318.77,7739.8) R75.1@7337.01,7721.56
GCLK1: R23.2 U1.29 | length 253.2
  TopLayer w12: U1.29@6287.1,8224.47 6482.06,8224.47 R23.2@6486.54,8220 ; 6440.73,8224.47 cw(c6440.73,8176.16) R23.2@6474.89,8210.32 ; 6462.33,8224.47 ccw(c6462.33,8242.24) R23.2@6474.89,8229.68
GGND: FB1.1 FB3.1 FB5.1 pad.0@4125,6193 pad.2@4140,6217 pad.10 pad.11 pad.12 | length 2792.6
  TopLayer w12: FB1.1@4573.32,6097.89 cw(c4549.96,6074.53) 4583,6074.53 cw(c4616.04,6074.53) FB1.1@4592.68,6097.89 ; pad.10@4578.76,6039.24 ccw(c4568.51,6049.49) 4583,6049.49 ccw(c4597.49,6049.49) pad.10@4587.24,6039.24 ; v3(4583,6035) FB1.1@4583,6109.54 ccw(c4646.5,6109.53) pad.10@4619.14,6052.23 ; pad.10@4583,6052.45 ccw(c4619.24,6052.45) pad.10@4603.63,6019.74 ; 4583,6071.48 ccw(c4628.33,6071.48) pad.10@4608.8,6030.57 ; FB1.1@4583,6090.51 ccw(c4637.41,6090.51) pad.10@4613.97,6041.4 ; pad.10@5183,6046 5183,6075 5197,6089 5458,6089 pad.11@5496,6051 ; 5454.32,6092.68 cw(c5415.14,6053.51) pad.11@5467.88,6036.53 ; 5468.21,6078.79 cw(c5436.16,6046.74) pad.11@5479.3,6032.86 ; 5482.09,6064.91 cw(c5457.17,6039.98) pad.11@5490.72,6029.18 ; FB3.1@7470.32,6094.89 cw(c7446.96,6071.53) 7480,6071.53 cw(c7513.04,6071.53) FB3.1@7489.68,6094.89 ; pad.11@7475.76,6037.24 ccw(c7465.51,6047.49) 7480,6047.49 ccw(c7494.49,6047.49) pad.11@7484.24,6037.24 ; v3(7480,6033) FB3.1@7480,6106.54 8727.46,6106.54 pad.12@8801,6033 ; FB3.1@7489.68,6096.86 cw(c7513.04,6073.5) 7513.04,6106.54 cw(c7513.04,6139.57) FB3.1@7489.68,6116.21 ; 8725.98,6108.02 cw(c8653.68,6035.71) pad.12@8755.63,6027.88 ; 8744.44,6089.56 cw(c8687.95,6033.08) pad.12@8767.6,6026.96 ; 8762.89,6071.11 cw(c8722.22,6030.45) pad.12@8779.56,6026.04 ; FB5.1@9323.79,6090.32 cw(c9300.43,6066.96) 9333.46,6066.96 cw(c9366.5,6066.96) FB5.1@9343.14,6090.32 ; pad.12@9329.22,6030.78 ccw(c9318.98,6041.02) 9333.46,6041.02 ccw(c9347.95,6041.02) pad.12@9337.71,6030.78 ; v3(9333.46,6026.54) FB5.1@9333.46,6100
  other v2: 10041,6014 9046,6021 9735,6024 6211,6025 4245,6028 4807,6028 6996,6029 5030,6030 4065,6031 4421,6032 5593,6033 5819,6033 6528,6033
